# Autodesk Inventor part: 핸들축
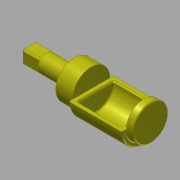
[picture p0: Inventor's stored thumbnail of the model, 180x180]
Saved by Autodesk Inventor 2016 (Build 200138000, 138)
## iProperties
Created: 2018-01
Part Number: 핸들축
Material: 강철, 연강
Document SubType Name: Modeling
Designer: mduedu
Density: 1 g/cm^3
Appearance: 노란색
Author: mduedu
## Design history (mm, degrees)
sketch "스케치1"
  geometry: L1 (0, 0)-(-38, 0); L2 (-38, 0)-(-38, -7.5); L3 (-38, -7.5)-(0, -7.5); L4 (0, -7.5)-(0, 0); L5 (-38, 0)-(-53, 0); L6 (-53, 0)-(-53, -16); L7 (-53, -16)-(-38, -16); L8 (-38, -16)-(-38, 0); L9 (-53, 0)-(-98, 0); L10 (-98, 0)-(-98, -19); L11 (-98, -19)-(-53, -19); L12 (-53, -19)-(-53, 0); L13 (-98, 0)-(-104, 0); L14 (-104, 0)-(-104, -15); L15 (-104, -15)-(-98, -15); L16 (-98, -15)-(-98, 0)
  constraints: 32 end point, 8 parallel, 4 horizontal, 4 perpendicular
  dimensions: "d0" = 6 distance of L14.end L15.end; "d2" = 30 diameter of L15 L13; "d3" = 32 diameter of L7 L5; "d4" = 15 distance of L6.end L7.end; "d5" = 45 distance of L10.end L11.end; "d6" = 38 diameter of L11 L9; "d7" = 38 distance of L2.end L3.end; "d8" = 15 diameter of L3 L1
revolve "회전1" sketch "스케치1" stored, may be unused: angle "d9" = 90 deg
sketch "스케치2"
  geometry: L1 (0, -7.5)-(0, 7.5) reference; L2 (0, 7.5)-(38, 7.5) reference; L3 (38, 7.5)-(38, 16) reference; L4 (38, 16)-(53, 16) reference; L5 (53, 16)-(53, 19) reference; L6 (53, 19)-(98, 19) reference; L7 (98, 19)-(98, 15) reference; L8 (98, 15)-(104, 15) reference; L9 (104, 15)-(104, -15) reference; L10 (104, -15)-(98, -15) reference; L11 (98, -15)-(98, -19) reference; L12 (98, -19)-(53, -19) reference; L13 (53, -19)-(53, -16) reference; L14 (53, -16)-(38, -16) reference; L15 (38, -16)-(38, -7.5) reference; L16 (38, -7.5)-(0, -7.5) reference; L17 (0, 0)-(104, 0); L18 (53, 19)-(53, 0); L19 (98, 19)-(98, 0); L20 (98, 0)-(53, 0); L21 (98, 19)-(53, 19)
  constraints: 10 end point, 3 perpendicular, 2 point on line, 1 midpoint, 1 parallel
extrude "돌출1" cut sketch "스케치2" stored distance "d10" = 10; taper "d11" = 0 deg
sketch "스케치3"
  geometry: L1 (45, 0)-(0, 0) reference; L2 (45, 4)-(45, 0) reference; L3 (45, 34)-(45, 4) reference; L4 (45, 38)-(45, 34) reference; L5 (0, 38)-(45, 38) reference; L6 (0, 35)-(0, 38) reference; L7 (0, 35)-(0, 3) reference; L8 (0, 0)-(0, 3) reference; L9 (0, 19)-(45, 19); L10 (4, 19)-(41, 19); L11 (41, 19)-(41, 34); L12 (41, 34)-(4, 34); L13 (4, 34)-(4, 19); 1 further point
  constraints: 10 end point, 2 midpoint, 2 parallel, 1 horizontal, 1 perpendicular, 1 point on line
  dimensions: "d12" = 4 distance between parallel lines of L3 L11; "d13" = 4 distance between parallel lines of L7 L13; "d14" = 4 distance between parallel lines of L12 L5
revolve "회전2" sketch "스케치3" stored, may be unused: angle "d15" = 90 deg
fillet "모깎기1" dims "d16" = 1
chamfer "모따기1" distance "d17" = 1; stored, may be unused: second distance "d18" = 2, angle "d19" = 45 deg
sketch "스케치4"
  geometry: L1 (-6, -6)-(-4.5, -6); L2 (6, -6)-(6, -4.5); L3 (6, 6)-(4.5, 6); L4 (-6, 6)-(-6, 4.5); L5 (-6, -6)-(6, 6); L6 (6, -6)-(-6, 6); L7 (-4.5, 6)-(-6, 6); L8 (-6, 4.5)-(-6, -4.5); L9 (-6, -4.5)-(-6, -6); L10 (-4.5, -6)-(4.5, -6); L11 (4.5, -6)-(6, -6); L12 (6, -4.5)-(6, 4.5); L13 (6, 4.5)-(6, 6); L14 (4.5, 6)-(-4.5, 6); C1 r 7.5 at (0, 0) reference; 2 further points
  constraints: 28 end point, 18 parallel, 9 perpendicular, 3 horizontal, 2 midpoint, 1 coincident, 11 other
  dimensions: "d20" = 12 distance of L4.start L3.start; "d21" = 12 distance of L3.start L2.start (= d20)
extrude "돌출2" cut sketch "스케치4" distance "d22" = 15; taper "d23" = 0 deg
chamfer "모따기2" distance "d24" = 1; stored, may be unused: second distance "d25" = 2, angle "d26" = 45 deg
sketch "스케치5"
  geometry: 2 further points
  constraints: 1 coincident
hole "구멍1" sketch "스케치5" at (5, 4.153) diameter "d27" = 2.459; stored, may be unused: countersink angle "d31" = 90 deg, drill point angle "d33" = 120 deg; dims "d28" = 6.9, "d29" = 4, "d30" = 2, "d32" = 8.4
node "솔리드1"
node "투영된 루프1"
node "절단 모서리 투영1"
